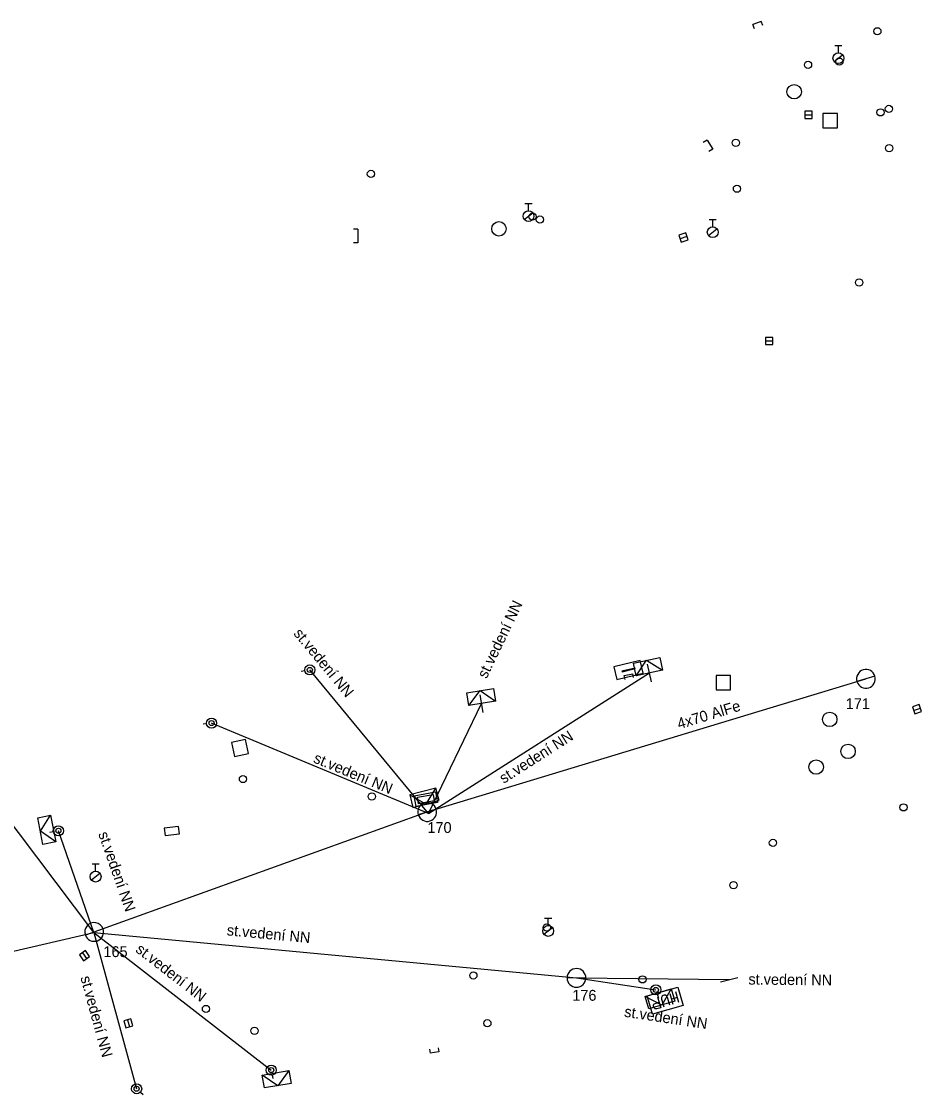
# Model space of a CAD drawing. Extents: x -584388 to -581645, y -1210859 to -1208922.
# Drawn here: x -583173.8 to -583111.5, y -1209557.8 to -1209483.5 of the extents above; entities that cross this region are included whole.
import ezdxf

# ---------------------------------------------------------------- set-up
doc = ezdxf.new("R2010")
doc.units = 0
for name, color, linetype in [('CIZÍ_NADZEM', 7, 'Continuous'), ('CIZÍ_PODZEM', 7, 'Continuous'), ('ELE_EON', 7, 'Continuous'), ('ELE_EON_POPIS', 7, 'Continuous')]:
    doc.layers.add(name, color=color, linetype=linetype)

msp = doc.modelspace()

# ---------------------------------------------------------------- linework, layer by layer
at = {"layer": 'CIZÍ_NADZEM'}
for p, q in [((-583117.5, -1209485.175), (-583117, -1209485.175)), ((-583117.25, -1209485.675), (-583117.25, -1209485.175)), ((-583117.544, -1209486.281), (-583116.954, -1209485.818)), ((-583119.56, -1209489.97), (-583119.06, -1209489.97)), ((-583117.32, -1209489.87), (-583118.32, -1209489.87)), ((-583118.32, -1209489.87), (-583118.32, -1209490.87)), ((-583117.32, -1209490.87), (-583117.32, -1209489.87)), ((-583118.32, -1209490.87), (-583117.32, -1209490.87)), ((-583138.95, -1209496.105), (-583138.45, -1209496.105)), ((-583138.7, -1209496.605), (-583138.7, -1209496.105)), ((-583138.994, -1209497.211), (-583138.404, -1209496.748)), ((-583126.244, -1209498.321), (-583125.654, -1209497.858)), ((-583126.2, -1209497.215), (-583125.7, -1209497.215)), ((-583125.95, -1209497.715), (-583125.95, -1209497.215)), ((-583127.733, -1209498.38), (-583128.207, -1209498.54)), ((-583122.29, -1209505.62), (-583121.79, -1209505.62)), ((-583124.71, -1209528.76), (-583125.71, -1209528.76)), ((-583125.71, -1209528.76), (-583125.71, -1209529.76)), ((-583124.71, -1209529.76), (-583124.71, -1209528.76)), ((-583125.71, -1209529.76), (-583124.71, -1209529.76)), ((-583112.046, -1209531.182), (-583111.574, -1209531.018)), ((-583158.294, -1209533.188), (-583159.272, -1209533.394)), ((-583159.272, -1209533.394), (-583159.066, -1209534.372)), ((-583158.088, -1209534.166), (-583158.294, -1209533.188)), ((-583159.066, -1209534.372), (-583158.088, -1209534.166)), ((-583168.964, -1209542.911), (-583168.374, -1209542.448)), ((-583168.92, -1209541.805), (-583168.42, -1209541.805)), ((-583168.67, -1209542.305), (-583168.67, -1209541.805)), ((-583137.634, -1209546.671), (-583137.044, -1209546.208)), ((-583137.59, -1209545.565), (-583137.09, -1209545.565)), ((-583137.34, -1209546.065), (-583137.34, -1209545.565)), ((-583169.582, -1209547.945), (-583169.298, -1209548.355)), ((-583166.468, -1209552.59), (-583166.332, -1209553.07))]:
    msp.add_line(p, q, dxfattribs=at)
for points in [[(-583122.49, -1209483.8), (-583122.6, -1209483.51), (-583123.16, -1209483.73)], [(-583123.05, -1209484.01), (-583123.16, -1209483.73)], [(-583132.01, -1209529.05), (-583132.07, -1209528.77), (-583131.48, -1209528.65)], [(-583131.43, -1209528.91), (-583131.48, -1209528.65)], [(-583127.995, -1209551.59), (-583130.107, -1209552.205), (-583130.476, -1209550.937), (-583128.364, -1209550.323), (-583127.995, -1209551.59)], [(-583128.283, -1209551.388), (-583128.498, -1209550.648)], [(-583129.551, -1209551.756), (-583129.825, -1209551.836), (-583129.924, -1209551.826), (-583129.966, -1209551.801), (-583130.015, -1209551.741), (-583130.046, -1209551.635), (-583130.037, -1209551.556), (-583130.015, -1209551.513), (-583129.937, -1209551.452), (-583129.662, -1209551.372)], [(-583129.766, -1209551.017), (-583129.551, -1209551.756)], [(-583128.917, -1209551.572), (-583129.071, -1209551.042), (-583129.131, -1209550.947), (-583129.217, -1209550.896), (-583129.316, -1209550.886), (-583129.377, -1209550.904), (-583129.456, -1209550.965), (-583129.496, -1209551.053), (-583129.495, -1209551.165), (-583129.341, -1209551.695)], [(-583128.923, -1209550.772), (-583128.707, -1209551.511)], [(-583128.384, -1209551.039), (-583128.809, -1209551.162)], [(-583145.55, -1209554.62), (-583145.51, -1209554.9)], [(-583144.95, -1209554.53), (-583144.91, -1209554.81), (-583145.51, -1209554.9)]]:
    msp.add_lwpolyline(points, dxfattribs=at)
for points in [[(-583119.56, -1209490.221), (-583119.06, -1209490.221), (-583119.06, -1209489.72), (-583119.56, -1209489.72)], [(-583127.814, -1209498.142), (-583128.288, -1209498.303), (-583128.127, -1209498.778), (-583127.653, -1209498.617)], [(-583122.29, -1209505.871), (-583121.79, -1209505.871), (-583121.79, -1209505.37), (-583122.29, -1209505.37)], [(-583111.964, -1209531.419), (-583111.491, -1209531.255), (-583111.655, -1209530.781), (-583112.128, -1209530.945)], [(-583163.859, -1209539.835), (-583162.865, -1209539.722), (-583162.921, -1209539.225), (-583163.915, -1209539.338)], [(-583169.789, -1209548.088), (-583169.503, -1209548.499), (-583169.091, -1209548.213), (-583169.377, -1209547.802)], [(-583166.71, -1209552.658), (-583166.573, -1209553.14), (-583166.091, -1209553.002), (-583166.227, -1209552.521)]]:
    msp.add_lwpolyline(points, close=True, dxfattribs=at)
for centre, radius in [((-583114.55, -1209484.19), 0.25), ((-583117.25, -1209486.05), 0.375), ((-583117.18, -1209486.29), 0.25), ((-583119.35, -1209486.51), 0.25), ((-583120.31, -1209488.37), 0.5), ((-583114.33, -1209489.8), 0.25), ((-583113.75, -1209489.56), 0.25), ((-583124.35, -1209491.91), 0.25), ((-583113.73, -1209492.28), 0.25), ((-583149.61, -1209494.06), 0.25), ((-583124.27, -1209495.08), 0.25), ((-583138.7, -1209496.98), 0.375), ((-583138.42, -1209497.01), 0.25), ((-583137.91, -1209497.22), 0.25), ((-583140.75, -1209497.86), 0.5), ((-583125.95, -1209498.09), 0.375), ((-583115.81, -1209501.57), 0.25), ((-583117.85, -1209531.8), 0.5), ((-583116.58, -1209534.02), 0.5), ((-583118.79, -1209535.1), 0.5), ((-583158.47, -1209535.93), 0.25), ((-583149.55, -1209537.14), 0.25), ((-583112.74, -1209537.89), 0.25), ((-583121.78, -1209540.35), 0.25), ((-583168.67, -1209542.68), 0.375), ((-583124.51, -1209543.27), 0.25), ((-583137.34, -1209546.44), 0.375), ((-583137.44, -1209546.2), 0.25), ((-583142.52, -1209549.52), 0.25), ((-583130.81, -1209549.79), 0.25), ((-583161.03, -1209551.84), 0.25), ((-583141.55, -1209552.83), 0.25), ((-583157.67, -1209553.35), 0.25)]:
    msp.add_circle(centre, radius, dxfattribs=at)
at = {"layer": 'CIZÍ_PODZEM'}
for points in [[(-583126.34, -1209491.72), (-583126.6, -1209491.88)], [(-583126.34, -1209491.72), (-583125.95, -1209492.35), (-583126.21, -1209492.51)], [(-583150.51, -1209497.88), (-583150.52, -1209498.82), (-583150.82, -1209498.82)], [(-583150.51, -1209497.88), (-583150.81, -1209497.88)]]:
    msp.add_lwpolyline(points, dxfattribs=at)
at = {"layer": 'ELE_EON'}
for p, q in [((-583130.189, -1209529.199), (-583130.471, -1209527.981)), ((-583154.184, -1209528.443), (-583154.43, -1209528.487)), ((-583114.718, -1209528.812), (-583115.962, -1209529.188)), ((-583141.844, -1209531.326), (-583142.056, -1209530.094)), ((-583160.987, -1209532.105), (-583161.235, -1209532.136)), ((-583145.088, -1209538.021), (-583146.332, -1209538.399)), ((-583171.594, -1209539.577), (-583171.839, -1209539.625)), ((-583168.158, -1209546.29), (-583169.382, -1209546.73)), ((-583134.73, -1209549.697), (-583136.03, -1209549.683)), ((-583125.417, -1209549.958), (-583124.203, -1209549.662)), ((-583129.78, -1209550.855), (-583129.708, -1209551.095)), ((-583156.45, -1209556.415), (-583156.406, -1209556.661)), ((-583165.57, -1209557.594), (-583165.383, -1209557.761))]:
    msp.add_line(p, q, dxfattribs=at)
for points in [[(-583168.79, -1209546.54), (-583187.13, -1209522.24)], [(-583145.62, -1209538.32), (-583153.84, -1209528.38)], [(-583131.246, -1209528.791), (-583130.522, -1209527.711), (-583129.414, -1209528.389)], [(-583168.77, -1209546.51), (-583145.71, -1209538.21), (-583115.34, -1209529)], [(-583145.62, -1209538.32), (-583130.33, -1209528.59)], [(-583142.825, -1209530.852), (-583142.046, -1209529.812), (-583140.975, -1209530.548)], [(-583145.62, -1209538.32), (-583141.95, -1209530.71)], [(-583145.62, -1209538.32), (-583160.64, -1209532.06)], [(-583146.928, -1209537.026), (-583145.793, -1209537.66), (-583145.114, -1209536.552)], [(-583171.434, -1209540.281), (-583172.494, -1209539.529), (-583171.786, -1209538.439)], [(-583168.79, -1209546.54), (-583171.25, -1209539.51)], [(-583201.09, -1209554.04), (-583168.79, -1209546.54)], [(-583168.79, -1209546.54), (-583165.83, -1209557.36)], [(-583168.79, -1209546.54), (-583156.51, -1209556.07)], [(-583168.79, -1209546.54), (-583135.38, -1209549.69)], [(-583135.38, -1209549.69), (-583129.88, -1209550.52)], [(-583135.38, -1209549.69), (-583124.81, -1209549.81)], [(-583128.822, -1209550.442), (-583129.463, -1209551.573), (-583130.618, -1209550.978)], [(-583155.285, -1209556.108), (-583156.064, -1209557.148), (-583157.135, -1209556.412)]]:
    msp.add_lwpolyline(points, dxfattribs=at)
for points in [[(-583131.438, -1209527.911), (-583129.607, -1209527.51), (-583129.414, -1209528.389), (-583131.246, -1209528.791)], [(-583132.582, -1209529.039), (-583130.758, -1209528.601), (-583130.968, -1209527.726), (-583132.792, -1209528.164)], [(-583132.226, -1209528.51), (-583131.315, -1209528.291), (-583131.324, -1209528.255), (-583132.235, -1209528.474)], [(-583142.971, -1209529.964), (-583141.121, -1209529.66), (-583140.975, -1209530.548), (-583142.825, -1209530.852)], [(-583146.7, -1209537.897), (-583144.886, -1209537.422), (-583145.114, -1209536.552), (-583146.928, -1209537.026)], [(-583146.616, -1209537.082), (-583145.141, -1209536.806), (-583145.003, -1209537.543), (-583146.477, -1209537.82)], [(-583146.391, -1209537.193), (-583145.31, -1209536.99), (-583145.227, -1209537.432), (-583146.308, -1209537.635)], [(-583172.318, -1209540.45), (-583172.67, -1209538.608), (-583171.786, -1209538.439), (-583171.434, -1209540.281)], [(-583128.565, -1209551.305), (-583130.362, -1209551.84), (-583130.618, -1209550.978), (-583128.822, -1209550.442)], [(-583155.139, -1209556.996), (-583156.989, -1209557.3), (-583157.135, -1209556.412), (-583155.285, -1209556.108)]]:
    msp.add_lwpolyline(points, close=True, dxfattribs=at)
for centre, radius in [((-583153.84, -1209528.38), 0.35), ((-583153.84, -1209528.38), 0.175), ((-583160.64, -1209532.06), 0.35), ((-583160.64, -1209532.06), 0.175), ((-583171.25, -1209539.51), 0.35), ((-583171.25, -1209539.51), 0.175), ((-583129.88, -1209550.52), 0.35), ((-583129.88, -1209550.52), 0.175), ((-583156.51, -1209556.07), 0.35), ((-583156.51, -1209556.07), 0.175), ((-583165.83, -1209557.36), 0.35), ((-583165.83, -1209557.36), 0.175)]:
    msp.add_circle(centre, radius, dxfattribs=at)
for centre, start, end in [((-583115.34, -1209529), 16.84118, 196.84118), ((-583115.34, -1209529), 196.84118, 16.84118), ((-583145.71, -1209538.21), 16.87046, 196.87046), ((-583145.71, -1209538.21), 196.87046, 16.87046), ((-583168.77, -1209546.51), 19.79535, 199.79535), ((-583168.77, -1209546.51), 199.79535, 19.79535), ((-583135.38, -1209549.69), 359.34956, 179.34956), ((-583135.38, -1209549.69), 179.34956, 359.34956)]:
    msp.add_arc(centre, 0.65, start, end, dxfattribs=at)

# ---------------------------------------------------------------- texts
at = {"layer": 'ELE_EON_POPIS'}
for s, rotation, p in [('st.vedení NN', 64.25384, (-583141.61, -1209529.03)), ('st.vedení NN', 309.58944, (-583155.01, -1209525.88)), ('4x70 AlFe', 16.87046, (-583128.28, -1209532.49)), ('st.vedení NN', 32.47118, (-583140.42, -1209536.27)), ('st.vedení NN', 337.37474, (-583153.65, -1209534.76)), ('st.vedení NN', 289.28639, (-583168.5, -1209539.71)), ('st.vedení NN', 354.61389, (-583159.61, -1209546.74)), ('st.vedení NN', 322.18643, (-583165.96, -1209547.84)), ('st.vedení NN', 285.29992, (-583169.73, -1209549.66)), ('st.vedení NN', 359.34956, (-583123.48, -1209550.15)), ('st.vedení NN', 351.41828, (-583132.11, -1209552.37))]:
    msp.add_text(s, height=0.75, rotation=rotation, dxfattribs=at).set_placement(p)
for s, p in [('171', (-583116.74, -1209531.09)), ('170', (-583145.7, -1209539.66)), ('165', (-583168.13, -1209548.25)), ('176', (-583135.67, -1209551.27))]:
    msp.add_text(s, height=0.75, dxfattribs=at).set_placement(p)

doc.saveas('drawing.dxf')
